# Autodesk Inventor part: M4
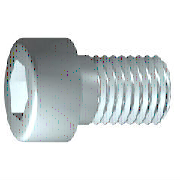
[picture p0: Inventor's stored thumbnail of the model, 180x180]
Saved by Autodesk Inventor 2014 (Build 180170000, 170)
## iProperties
IsCustomPart: 0
Company: 한국ATC센터
Created: 2014-10
Part Number: M4
Material: Steel, Mild
Description: 6각머리 태핑 나사
Document SubType Name: Modeling
Standard: KS B 1003
Designer: KYOUNG IL JANG
Standards Organization: KS
Language: ko-KR
Size Designation: M 4 x 10
Categories: <MemberInstance><Categories><Category DisplayName="조임쇠" InternalName="e4da775c-781d-43d5-af7c-5136215cf5a6" Mnemonic="FSTN"><Category DisplayName="볼트" InternalN
Density: 7.86 g/cm^3
Mass: 2.0371 g
Surface Area: 3.0572 cm^2
Volume: 0.259174 cm^3
Appearance: Black Cast
Author: KYOUNG IL JANG
Revision Number: 1
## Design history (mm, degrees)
revolve "본체" stored, may be unused: angle "d10" = 90 deg
sketch "스케치2"
  geometry: L1 (0, -4.9)-(0, 4.9) reference; L2 (-4.9, 0)-(4.9, 0) reference; L3 (1.732, 0)-(0.866, -1.5); L4 (0.866, -1.5)-(-0.866, -1.5); L5 (-0.866, -1.5)-(-1.732, 0); L6 (-1.732, 0)-(-0.866, 1.5); L7 (-0.866, 1.5)-(0.866, 1.5); L8 (0.866, 1.5)-(1.732, 0); 2 further points
  constraints: 12 end point, 1 coincident, 1 horizontal alignment, 1 point on line, 12 other
extrude "슬롯" join sketch "스케치2" stored distance "d11" = 10; taper "d12" = 0 deg
workplane "Work Plane1"
fillet "Fillet2" dims "d30" = 0.1 (= R)
body "Solid1"
fillet "모깎기1" dims "d17" = 0.4 (= RR)
feature "스레드" dims "d13" = 8.25 (= GEL), "d14" = 0
chamfer "모따기1" distance "d15" = 0.42941 (= -0.5 x SPD + 0.5 x GD); stored, may be unused: second distance "d16" = 0.42941 (= GUL), angle "d27" = 45 deg
sketch "스케치1"
  geometry: L1 (-1, 0)-(10, 0); L2 (10, 0)-(10, 2); L3 (10, 2)-(1.75, 2); L4 (1.75, 2)-(1.32, 2); L5 (1.32, 2)-(0, 2); L6 (0, 2)-(0, 3.5); L7 (0, 3.5)-(-4, 3.5); L8 (-4, 3.5)-(-4, 1.732); L9 (-4, 1.732)-(-2, 1.732); L10 (-2, 1.732)-(-1, 0); L11 (-6.8, 0)-(12.8, 0) reference; L12 (0, -0.7)-(0, 4.2) reference; L13 (1.75, 2)-(0, 2)
  constraints: 22 end point, 6 parallel, 2 collinear, 2 perpendicular, 1 horizontal, 1 point on line
  dimensions: "d1" = 8.25 distance from line of L3.end L2 (= GEL); "d2" = 0.42952 distance of L4.end L3.end (computed from GAL); "d3" = 4 distance between parallel lines of L8 L6 (= KOH); "d4" = 2 distance of L8.end L9.end (= INTI); "d5" = 60 deg angle of L10 L1; "d6" = 4 diameter of L3 L1 (= GD); "d7" = 4 diameter of L5 L1 (= BDM); "d8" = 3.4641 diameter of L9 L1 (= 1.1547 x SW); "d9" = 7 diameter of L7 L1 (= KOD); "d26" = 10 distance between parallel lines of L12 L2 (= NLG)
other parameters: "GD" = 4 (= NND) [user parameter; used in 2 equation terms], "NLG" = 10 [user parameter; used in 1 equation term], "GEL" = 8.25 [user parameter; used in 2 equation terms], "KOD" = 7 [user parameter; used in 1 equation term], "KOH" = 4 [user parameter; used in 1 equation term], "INTI" = 2 [user parameter; used in 1 equation term], "GAL" = 0.42941 (= 0.61345 x PTC) [user parameter; used in 1 equation term], "GUL" = 0.42941 (= 0.61345 x PTC) [user parameter; used in 1 equation term], "BDM" = 4 (= NND) [user parameter; used in 1 equation term], "SW" = 3 [user parameter; used in 2 equation terms], "RR" = 0.4 [user parameter; used in 1 equation term], "SPD" = 3.14117 (= NND - 1.2269 x PTC) [user parameter; used in 1 equation term], "d19" = 0, "d28" = 0, "d29" = 0, "R" = 0.1 [user parameter; used in 1 equation term], "PHH" = 0.2 [user parameter], "GD1" = 3.14117 (= THREADDIA - 1.2269 x PTC) [user parameter], "THREADDIA" = 4 [user parameter; used in 1 equation term], "FAWI" = 45 deg [user parameter], "TPU" = 14.28571 (computed from PTC) [user parameter], "PTC" = 0.7 [user parameter; used in 5 equation terms], "NND" = 4 [user parameter; used in 3 equation terms], "TOA" = 30 deg [user parameter], "E0" = 3.465 (= 1.155 x SW) [user parameter]
